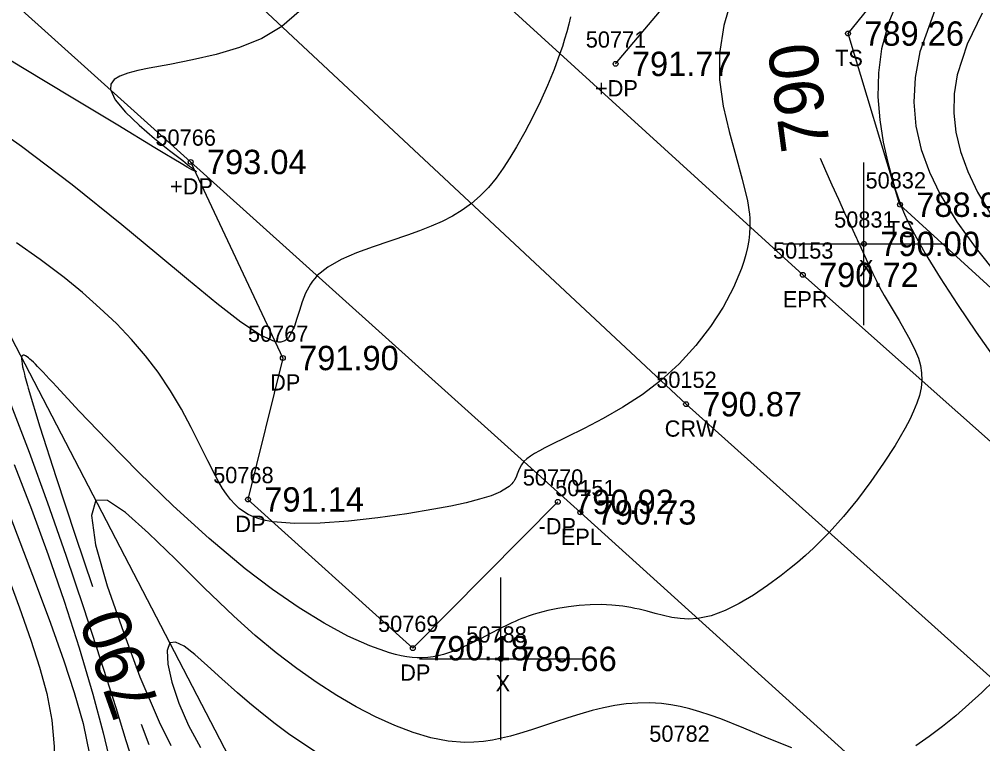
# Model space of a CAD drawing. Extents: x 1378535 to 1380697, y 997729 to 1000024.
# Drawn here: x 1378746.7 to 1378805.9, y 999754.2 to 999798.8 of the extents above; entities that cross this region are included whole.
import ezdxf

# ---------------------------------------------------------------- set-up
doc = ezdxf.new("R2010")
doc.units = 0
for name, color, linetype in [('RD_DTM_BkLn1', 7, 'Continuous'), ('RD_DTM_BkLn2', 7, 'Continuous'), ('RD_DTM_BkLn_txCode', 7, 'Continuous'), ('RD_DTM_Major1', 7, 'Continuous'), ('RD_DTM_Major1_Lbl', 7, 'Continuous'), ('RD_DTM_Minor1', 7, 'Continuous'), ('RD_EX_Driveway', 7, 'Continuous'), ('RD_EX_Driveway_txCode', 7, 'Continuous'), ('RD_EX_Misc', 7, 'Continuous'), ('RD_EX_Misc_txCode', 7, 'Continuous'), ('RD_EX_Road', 7, 'Continuous'), ('RD_EX_Road_txCode', 7, 'Continuous'), ('RD_EX_TX_Driveway_ELEV', 7, 'Continuous'), ('RD_EX_TX_Misc_ELEV', 7, 'Continuous'), ('RD_EX_TX_Road_ELEV', 7, 'Continuous'), ('RD_HC_Survey_ELEV', 7, 'Continuous'), ('RD_HC_Survey_txCode', 7, 'Continuous'), ('RD_SMD_Locator', 7, 'Continuous')]:
    doc.layers.add(name, color=color, linetype=linetype)

msp = doc.modelspace()

# ---------------------------------------------------------------- linework, layer by layer
at = {"layer": 'RD_DTM_BkLn1'}
msp.add_lwpolyline([(1379201.7, 999398.205), (1379156.533, 999438.891), (1379112.084, 999479.847), (1379066.495, 999520.561), (1379020.821, 999562.613), (1378974.239, 999604.981), (1378928.957, 999646.778), (1378882.739, 999688.619), (1378834.578, 999733.071), (1378787.698, 999775.121), (1378743.642, 999816.274), (1378698.706, 999856.431), (1378652.056, 999898.787), (1378607.023, 999939.646), (1378604.538, 999941.267)], dxfattribs=at)
at = {"layer": 'RD_DTM_BkLn2'}
for points in [[(1378760.972, 999750.758), (1378735.038, 999800.678), (1378693.628, 999839.142), (1378650.843, 999877.81), (1378599.986, 999906.202), (1378575.293, 999908.279)], [(1378925.231, 999671.641), (1378884.865, 999710.355), (1378842.861, 999749.051), (1378800.856, 999787.394), (1378797.661, 999797.924), (1378813.033, 999816.9), (1378834.932, 999844.694), (1378855.626, 999872.588)]]:
    msp.add_lwpolyline(points, dxfattribs=at)
at = {"layer": 'RD_DTM_Major1'}
for points in [[(1378795.953, 999790.267), (1378796.277, 999789.503), (1378796.671, 999788.609), (1378797.066, 999787.741), (1378797.454, 999786.902), (1378797.83, 999786.095), (1378798.187, 999785.325), (1378798.216, 999785.261), (1378798.245, 999785.198), (1378798.273, 999785.135), (1378798.302, 999785.073), (1378798.33, 999785.011), (1378798.359, 999784.949), (1378798.569, 999784.485), (1378798.774, 999784.034), (1378798.976, 999783.595), (1378799.179, 999783.166), (1378799.386, 999782.744), (1378799.601, 999782.329), (1378799.89, 999781.805), (1378800.19, 999781.286), (1378800.496, 999780.773), (1378800.802, 999780.263), (1378801.1, 999779.755), (1378801.386, 999779.248), (1378801.613, 999778.818), (1378801.817, 999778.385), (1378801.987, 999777.946), (1378802.115, 999777.499), (1378802.191, 999777.041), (1378802.204, 999776.569), (1378802.156, 999776.124), (1378802.052, 999775.663), (1378801.898, 999775.187), (1378801.697, 999774.692), (1378801.455, 999774.179), (1378801.175, 999773.645), (1378800.562, 999772.586), (1378799.854, 999771.481), (1378799.072, 999770.361), (1378798.239, 999769.258), (1378797.374, 999768.203), (1378796.499, 999767.226), (1378796.015, 999766.727), (1378795.532, 999766.258), (1378795.047, 999765.813), (1378794.557, 999765.389), (1378794.061, 999764.981), (1378793.555, 999764.584), (1378792.708, 999763.956), (1378791.841, 999763.371), (1378790.967, 999762.851), (1378790.097, 999762.421), (1378789.244, 999762.105), (1378788.421, 999761.927), (1378787.871, 999761.894), (1378787.337, 999761.924), (1378786.816, 999762.003), (1378786.305, 999762.116), (1378785.8, 999762.246), (1378785.297, 999762.381), (1378785.051, 999762.443), (1378784.804, 999762.502), (1378784.555, 999762.557), (1378784.305, 999762.608), (1378784.054, 999762.653), (1378783.799, 999762.691), (1378783.139, 999762.76), (1378782.466, 999762.788), (1378781.791, 999762.778), (1378781.119, 999762.734), (1378780.459, 999762.659), (1378779.818, 999762.557), (1378779.5, 999762.495), (1378779.189, 999762.427), (1378778.883, 999762.351), (1378778.582, 999762.268), (1378778.285, 999762.177), (1378777.991, 999762.078), (1378777.788, 999762.003), (1378777.587, 999761.925), (1378777.386, 999761.842), (1378777.185, 999761.755), (1378776.983, 999761.665), (1378776.781, 999761.57), (1378776.226, 999761.296), (1378775.665, 999761.007), (1378775.099, 999760.713), (1378774.531, 999760.427), (1378773.963, 999760.16), (1378773.395, 999759.925), (1378773.083, 999759.813), (1378772.771, 999759.716), (1378772.455, 999759.636), (1378772.133, 999759.574), (1378771.805, 999759.533), (1378771.469, 999759.513), (1378771.162, 999759.516), (1378770.845, 999759.538), (1378770.517, 999759.579), (1378770.177, 999759.639), (1378769.822, 999759.72), (1378769.451, 999759.821), (1378768.241, 999760.247), (1378766.897, 999760.854), (1378765.439, 999761.637), (1378763.887, 999762.591), (1378762.259, 999763.71), (1378760.576, 999764.99), (1378758.357, 999766.855), (1378756.153, 999768.869), (1378754.038, 999770.922), (1378752.085, 999772.902), (1378750.368, 999774.699), (1378748.963, 999776.204), (1378748.736, 999776.449), (1378748.523, 999776.679), (1378748.323, 999776.894), (1378748.137, 999777.093), (1378747.963, 999777.276), (1378747.803, 999777.443), (1378747.67, 999777.577), (1378747.547, 999777.698), (1378747.434, 999777.806), (1378747.331, 999777.899), (1378747.237, 999777.978), (1378747.152, 999778.041), (1378747.06, 999778.099), (1378746.983, 999778.133), (1378746.92, 999778.141), (1378746.871, 999778.122), (1378746.838, 999778.076), (1378746.819, 999778.001), (1378746.815, 999777.9), (1378746.825, 999777.77), (1378746.848, 999777.612), (1378746.885, 999777.424), (1378746.934, 999777.207), (1378746.995, 999776.96), (1378747.027, 999776.835), (1378747.062, 999776.703), (1378747.1, 999776.564), (1378747.14, 999776.42), (1378747.183, 999776.268), (1378747.228, 999776.11), (1378747.95, 999773.717), (1378748.942, 999770.616), (1378750.121, 999767.051), (1378751.186, 999763.911)], [(1378754.181, 999755.424), (1378754.644, 999754.176)]]:
    msp.add_lwpolyline(points, dxfattribs=at)
at = {"layer": 'RD_DTM_Minor1'}
for points in [[(1378790.522, 999800.142), (1378790.012, 999798.429), (1378789.747, 999796.693), (1378789.764, 999795.067), (1378789.987, 999793.463), (1378790.342, 999791.899), (1378790.757, 999790.395), (1378791.157, 999788.967), (1378791.468, 999787.634), (1378791.517, 999787.358), (1378791.558, 999787.086), (1378791.59, 999786.819), (1378791.613, 999786.555), (1378791.627, 999786.294), (1378791.629, 999786.036), (1378791.61, 999785.608), (1378791.563, 999785.183), (1378791.487, 999784.758), (1378791.384, 999784.33), (1378791.257, 999783.898), (1378791.104, 999783.458), (1378790.611, 999782.296), (1378789.974, 999781.099), (1378789.202, 999779.897), (1378788.301, 999778.722), (1378787.281, 999777.603), (1378786.147, 999776.569), (1378784.997, 999775.701), (1378783.798, 999774.927), (1378782.593, 999774.24), (1378781.424, 999773.631), (1378780.335, 999773.094), (1378779.369, 999772.619), (1378779.006, 999772.435), (1378778.676, 999772.259), (1378778.38, 999772.089), (1378778.121, 999771.921), (1378777.901, 999771.755), (1378777.723, 999771.587), (1378777.574, 999771.398), (1378777.466, 999771.206), (1378777.383, 999771.014), (1378777.312, 999770.823), (1378777.238, 999770.636), (1378777.147, 999770.454), (1378777.096, 999770.372), (1378777.037, 999770.292), (1378776.97, 999770.213), (1378776.895, 999770.136), (1378776.81, 999770.06), (1378776.715, 999769.987), (1378776.277, 999769.729), (1378775.702, 999769.491), (1378774.999, 999769.267), (1378774.173, 999769.056), (1378773.234, 999768.853), (1378772.188, 999768.656), (1378770.522, 999768.379), (1378768.741, 999768.13), (1378766.935, 999767.932), (1378765.193, 999767.809), (1378763.607, 999767.786), (1378762.267, 999767.887), (1378761.827, 999767.965), (1378761.433, 999768.066), (1378761.08, 999768.191), (1378760.762, 999768.338), (1378760.473, 999768.51), (1378760.209, 999768.706), (1378759.928, 999768.963), (1378759.666, 999769.253), (1378759.421, 999769.576), (1378759.185, 999769.932), (1378758.955, 999770.321), (1378758.725, 999770.744), (1378758.274, 999771.637), (1378757.79, 999772.627), (1378757.259, 999773.692), (1378756.664, 999774.807), (1378755.99, 999775.949), (1378755.221, 999777.095), (1378754.444, 999778.104), (1378753.586, 999779.097), (1378752.649, 999780.075), (1378751.641, 999781.037), (1378750.567, 999781.984), (1378749.432, 999782.916), (1378747.969, 999784.032), (1378746.504, 999785.054)], [(1378800.827, 999800.231), (1378800.171, 999798.621), (1378799.724, 999796.994), (1378799.526, 999795.509), (1378799.5, 999794.038), (1378799.612, 999792.609), (1378799.825, 999791.249), (1378800.104, 999789.988), (1378800.413, 999788.853), (1378800.545, 999788.417), (1378800.68, 999788.002), (1378800.822, 999787.6), (1378800.974, 999787.203), (1378801.14, 999786.805), (1378801.325, 999786.398), (1378801.374, 999786.295), (1378801.424, 999786.191), (1378801.476, 999786.085), (1378801.584, 999785.871), (1378801.64, 999785.762), (1378802.398, 999784.4), (1378803.326, 999782.888), (1378804.387, 999781.262), (1378805.545, 999779.555), (1378806.765, 999777.803)], [(1378763.891, 999799.271), (1378762.831, 999798.349), (1378761.602, 999797.627), (1378760.232, 999797.066), (1378758.788, 999796.633), (1378757.335, 999796.297), (1378755.936, 999796.026), (1378754.659, 999795.789), (1378753.964, 999795.646), (1378753.361, 999795.49), (1378752.869, 999795.308), (1378752.512, 999795.087), (1378752.309, 999794.814), (1378752.283, 999794.476), (1378752.584, 999793.839), (1378753.211, 999793.087), (1378754.052, 999792.279), (1378754.993, 999791.473), (1378755.922, 999790.729), (1378756.729, 999790.106), (1378756.886, 999789.985), (1378757.029, 999789.874), (1378757.158, 999789.774), (1378757.27, 999789.686), (1378757.366, 999789.61), (1378757.443, 999789.547), (1378757.507, 999789.491), (1378757.547, 999789.452), (1378757.564, 999789.43), (1378757.557, 999789.422), (1378757.529, 999789.43), (1378757.48, 999789.452), (1378757.295, 999789.549), (1378757.013, 999789.71), (1378756.64, 999789.93), (1378756.18, 999790.205), (1378755.639, 999790.531), (1378755.023, 999790.902), (1378752.736, 999792.279), (1378749.965, 999793.947), (1378746.874, 999795.813), (1378743.627, 999797.779)], [(1378802.996, 999799.354), (1378802.085, 999796.793), (1378801.787, 999795.226), (1378801.71, 999793.708), (1378801.839, 999792.235), (1378802.162, 999790.8), (1378802.664, 999789.395), (1378803.332, 999788.014), (1378804.356, 999786.342), (1378805.546, 999784.697), (1378806.839, 999783.081)], [(1378805.923, 999799.176), (1378804.989, 999797.264), (1378804.378, 999795.385), (1378804.19, 999794.206), (1378804.163, 999793.033), (1378804.294, 999791.854), (1378804.583, 999790.657), (1378805.026, 999789.431), (1378805.621, 999788.163), (1378807.276, 999785.428)], [(1378780.593, 999798.963), (1378780.479, 999798.496), (1378780.358, 999798.038), (1378780.228, 999797.586), (1378780.089, 999797.137), (1378779.94, 999796.688), (1378779.582, 999795.711), (1378779.179, 999794.731), (1378778.739, 999793.756), (1378778.269, 999792.796), (1378777.776, 999791.86), (1378777.268, 999790.958), (1378776.864, 999790.284), (1378776.448, 999789.641), (1378776.01, 999789.032), (1378775.543, 999788.462), (1378775.039, 999787.937), (1378774.489, 999787.459), (1378773.928, 999787.059), (1378773.325, 999786.698), (1378772.683, 999786.37), (1378772.006, 999786.069), (1378771.299, 999785.79), (1378770.564, 999785.524), (1378768.438, 999784.803), (1378767.414, 999784.426), (1378766.472, 999784.016), (1378765.654, 999783.556), (1378765.003, 999783.031), (1378764.85, 999782.863), (1378764.713, 999782.689), (1378764.59, 999782.509), (1378764.48, 999782.324), (1378764.38, 999782.134), (1378764.29, 999781.941), (1378764.083, 999781.416), (1378763.911, 999780.889), (1378763.756, 999780.384), (1378763.603, 999779.921), (1378763.434, 999779.522), (1378763.234, 999779.209), (1378763.134, 999779.106), (1378763.024, 999779.025), (1378762.899, 999778.969), (1378762.758, 999778.939), (1378762.598, 999778.937), (1378762.417, 999778.966), (1378761.522, 999779.364), (1378760.317, 999780.169), (1378758.83, 999781.316), (1378757.092, 999782.741), (1378755.132, 999784.376), (1378752.982, 999786.158), (1378749.932, 999788.606), (1378746.809, 999790.982), (1378743.818, 999793.077)], [(1378746.156, 999775.097), (1378747.279, 999772.171), (1378748.414, 999769.055), (1378749.538, 999765.838), (1378750.628, 999762.606), (1378751.661, 999759.447), (1378752.613, 999756.448), (1378753.238, 999754.437), (1378753.82, 999752.573)], [(1378746.371, 999771.416), (1378747.428, 999768.657), (1378748.453, 999765.844), (1378749.432, 999762.998), (1378750.351, 999760.136), (1378751.198, 999757.279), (1378751.839, 999754.902), (1378752.386, 999752.58), (1378752.808, 999750.352), (1378753.07, 999748.258), (1378753.14, 999746.335), (1378752.985, 999744.622), (1378752.824, 999743.885), (1378752.606, 999743.192), (1378752.336, 999742.529), (1378752.016, 999741.883), (1378751.65, 999741.24), (1378751.24, 999740.588), (1378750.125, 999738.971), (1378748.834, 999737.247), (1378747.411, 999735.436), (1378745.904, 999733.56)], [(1378794.2, 999753.97), (1378792.712, 999754.573), (1378791.243, 999755.191), (1378789.836, 999755.754), (1378789.18, 999755.99), (1378788.546, 999756.196), (1378787.932, 999756.37), (1378787.336, 999756.512), (1378786.754, 999756.621), (1378786.185, 999756.696), (1378785.445, 999756.742), (1378784.721, 999756.733), (1378784.008, 999756.675), (1378783.306, 999756.574), (1378782.61, 999756.436), (1378781.919, 999756.267), (1378781.167, 999756.054), (1378780.417, 999755.821), (1378779.67, 999755.575), (1378778.927, 999755.327), (1378778.186, 999755.084), (1378777.45, 999754.855), (1378776.899, 999754.699), (1378776.347, 999754.561), (1378775.791, 999754.447), (1378775.226, 999754.364), (1378774.65, 999754.315), (1378774.059, 999754.308), (1378773.054, 999754.394), (1378772.003, 999754.599), (1378770.908, 999754.917), (1378769.773, 999755.344), (1378768.601, 999755.875), (1378767.395, 999756.503), (1378766.21, 999757.194), (1378764.997, 999757.974), (1378763.757, 999758.847), (1378762.49, 999759.818), (1378761.197, 999760.891), (1378759.877, 999762.071), (1378758.058, 999763.818), (1378756.282, 999765.587), (1378754.636, 999767.194), (1378753.212, 999768.457), (1378752.097, 999769.193), (1378751.381, 999769.219), (1378751.126, 999768.269), (1378751.373, 999766.456), (1378752.093, 999763.937), (1378753.083, 999761.091), (1378754.084, 999758.337), (1378755.291, 999755.572), (1378755.994, 999754.119)], [(1378745.929, 999768.695), (1378747.714, 999764.008), (1378748.592, 999761.653), (1378749.425, 999759.32), (1378750.063, 999757.39), (1378750.601, 999755.475), (1378750.988, 999753.561), (1378751.173, 999751.634), (1378751.107, 999749.678), (1378750.74, 999747.678), (1378749.714, 999744.879), (1378748.194, 999742.039), (1378746.338, 999739.227)], [(1378745.95, 999764.604), (1378746.693, 999762.592), (1378747.391, 999760.599), (1378747.92, 999758.949), (1378748.363, 999757.313), (1378748.679, 999755.684), (1378748.832, 999754.05), (1378748.783, 999752.404), (1378748.495, 999750.735), (1378747.682, 999748.42), (1378746.467, 999746.078)], [(1378765.016, 999753.638), (1378764.112, 999754.236), (1378763.244, 999754.844), (1378762.41, 999755.461), (1378761.61, 999756.086), (1378760.841, 999756.718), (1378760.101, 999757.356), (1378759.144, 999758.219), (1378758.263, 999759.027), (1378757.478, 999759.717), (1378756.815, 999760.224), (1378756.296, 999760.485), (1378755.944, 999760.436), (1378755.769, 999759.968), (1378755.814, 999759.129), (1378756.06, 999758.015), (1378756.489, 999756.724), (1378757.082, 999755.349), (1378757.822, 999753.989)], [(1378806.651, 999758.121), (1378805.884, 999757.383), (1378805.095, 999756.656), (1378804.288, 999755.952), (1378803.471, 999755.284), (1378802.649, 999754.665), (1378801.828, 999754.108)]]:
    msp.add_lwpolyline(points, dxfattribs=at)
at = {"layer": 'RD_EX_Driveway'}
for points in [[(1378783.362, 999796.058), (1378793.727, 999808.347), (1378786.986, 999814.964), (1378768.645, 999809.205)], [(1378757.219, 999790.023), (1378762.889, 999777.961), (1378760.747, 999769.258), (1378770.891, 999760.107), (1378779.811, 999769.111)]]:
    msp.add_lwpolyline(points, dxfattribs=at)
at = {"layer": 'RD_EX_Misc'}
for p, q in [((1378798.642, 999779.982), (1378798.642, 999789.982)), ((1378793.642, 999784.982), (1378803.642, 999784.982)), ((1378776.297, 999754.45), (1378776.297, 999764.45)), ((1378771.297, 999759.45), (1378781.297, 999759.45))]:
    msp.add_line(p, q, dxfattribs=at)
at = {"layer": 'RD_EX_Road'}
for points in [[(1379209.475, 999405.54), (1379163.997, 999446.485), (1379118.805, 999488.017), (1379074.408, 999528.841), (1379028.669, 999569.9), (1378981.979, 999612.718), (1378937.166, 999653.911), (1378890.129, 999696.785), (1378842.566, 999740.72), (1378794.879, 999783.075), (1378749.806, 999824.149), (1378706.231, 999863.66), (1378659.579, 999905.32), (1378614.058, 999947.757), (1378610.306, 999950.384)], [(1379194.921, 999391.17), (1379151.382, 999431.093), (1379105.356, 999472.756), (1379062.213, 999513.117), (1379014.238, 999555.894), (1378967.91, 999597.354), (1378922.421, 999639.979), (1378876.774, 999681.523), (1378827.896, 999726.217), (1378781.196, 999768.463), (1378736.445, 999808.724), (1378691.95, 999849.175), (1378644.395, 999891.391), (1378600.504, 999932.423), (1378598.568, 999933.73)]]:
    msp.add_lwpolyline(points, dxfattribs=at)
at = {"layer": 'RD_SMD_Locator'}
for centre in [(1378797.661, 999797.924), (1378783.362, 999796.058), (1378757.219, 999790.023), (1378800.856, 999787.394), (1378798.642, 999784.982), (1378794.879, 999783.075), (1378762.889, 999777.961), (1378787.698, 999775.121), (1378760.747, 999769.258), (1378779.811, 999769.111), (1378781.196, 999768.463), (1378770.891, 999760.107), (1378776.297, 999759.45)]:
    msp.add_circle(centre, 0.15, dxfattribs=at)

# ---------------------------------------------------------------- texts
at = {"layer": 'RD_DTM_BkLn_txCode'}
for s, p in [('TS', (1378796.866, 999795.924)), ('50832', (1378798.738, 999788.394)), ('TS', (1378800.061, 999785.394)), ('50782', (1378785.435, 999754.349))]:
    msp.add_text(s, height=1, dxfattribs=at).set_placement(p)
at = {"layer": 'RD_DTM_Major1_Lbl'}
for rotation, p in [(97.60919, (1378796.564, 999790.873)), (109.43715, (1378755.371, 999756.482))]:
    msp.add_text('790', height=3, rotation=rotation, dxfattribs=at).set_placement(p)
at = {"layer": 'RD_EX_Driveway_txCode'}
for s, p in [('50771', (1378781.527, 999797.058)), ('+DP', (1378782.094, 999794.058)), ('50766', (1378755.054, 999791.023)), ('+DP', (1378755.951, 999788.023)), ('50767', (1378760.747, 999778.961)), ('DP', (1378762.109, 999775.961)), ('50768', (1378758.605, 999770.258)), ('50770', (1378777.654, 999770.111)), ('DP', (1378759.967, 999767.258)), ('-DP', (1378778.622, 999767.111)), ('50769', (1378768.749, 999761.107)), ('DP', (1378770.111, 999758.107))]:
    msp.add_text(s, height=1, dxfattribs=at).set_placement(p)
at = {"layer": 'RD_EX_Misc_txCode'}
for s, p in [('50831', (1378796.807, 999785.982)), ('X', (1378798.327, 999782.982)), ('50788', (1378774.179, 999760.45)), ('X', (1378775.982, 999757.45))]:
    msp.add_text(s, height=1, dxfattribs=at).set_placement(p)
at = {"layer": 'RD_EX_Road_txCode'}
for s, p in [('50153', (1378793.044, 999784.075)), ('EPR', (1378793.651, 999781.075)), ('50151', (1378779.645, 999769.463)), ('EPL', (1378779.991, 999766.463))]:
    msp.add_text(s, height=1, dxfattribs=at).set_placement(p)
at = {"layer": 'RD_EX_TX_Driveway_ELEV'}
for s, p in [('791.77', (1378784.362, 999795.308)), ('793.04', (1378758.219, 999789.273)), ('791.90', (1378763.889, 999777.211)), ('791.14', (1378761.747, 999768.508)), ('790.92', (1378780.811, 999768.361)), ('790.18', (1378771.891, 999759.357))]:
    msp.add_text(s, height=1.5, dxfattribs=at).set_placement(p)
at = {"layer": 'RD_EX_TX_Misc_ELEV'}
for s, p in [('789.26', (1378798.661, 999797.174)), ('788.96', (1378801.856, 999786.644)), ('790.00', (1378799.642, 999784.232)), ('789.66', (1378777.297, 999758.7))]:
    msp.add_text(s, height=1.5, dxfattribs=at).set_placement(p)
at = {"layer": 'RD_EX_TX_Road_ELEV'}
for s, p in [('790.72', (1378795.879, 999782.325)), ('790.73', (1378782.196, 999767.713))]:
    msp.add_text(s, height=1.5, dxfattribs=at).set_placement(p)
at = {"layer": 'RD_HC_Survey_ELEV'}
msp.add_text('790.87', height=1.5, dxfattribs=at).set_placement((1378788.698, 999774.371))
at = {"layer": 'RD_HC_Survey_txCode'}
for s, p in [('50152', (1378785.863, 999776.121)), ('CRW', (1378786.383, 999773.121))]:
    msp.add_text(s, height=1, dxfattribs=at).set_placement(p)

doc.saveas('drawing.dxf')
